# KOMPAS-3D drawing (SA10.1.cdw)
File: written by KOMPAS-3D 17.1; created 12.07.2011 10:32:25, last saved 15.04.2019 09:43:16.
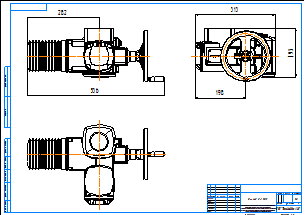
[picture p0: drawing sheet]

Title block, sheet 1: name: Привод SA 10.1; material: Внимание! Данный продукт является объектом авторского права ООО «Торговый Дом АДЛ». / Запрещается изменение, копирование, распространение / (в том числе путем копирования на другие сайты и ресурсы в Интернете) / или любое иное использование информации и объектов без предварительного / согласия правообладателя (ООО «Торговый Дом АДЛ»).; scale: 1:2; sheets: 1; organisation: ООО "Торговый дом АДЛ"; sheet format: A2; stored path: \\adlc.lan\data\АДЛ_ПКД\3D-модели\Поставщики\Сервоприводы AUMA\Электроприводы серии SA\KOMPAS 2D\Привод SA 10.1.cdw

Views: Проекционный вид 2, Проекционный вид 4, Проекционный вид 6
Dimensions and other numbers on the sheet: 193; 198; 313; 536; 282; 1:2; 1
